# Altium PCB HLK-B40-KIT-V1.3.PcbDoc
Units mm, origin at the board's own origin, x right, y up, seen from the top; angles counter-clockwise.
Board outline 52 x 33 mm, 2 copper layers (Top Layer, Bottom Layer); 41 components, 44 nets, 164 pads, 113 vias.
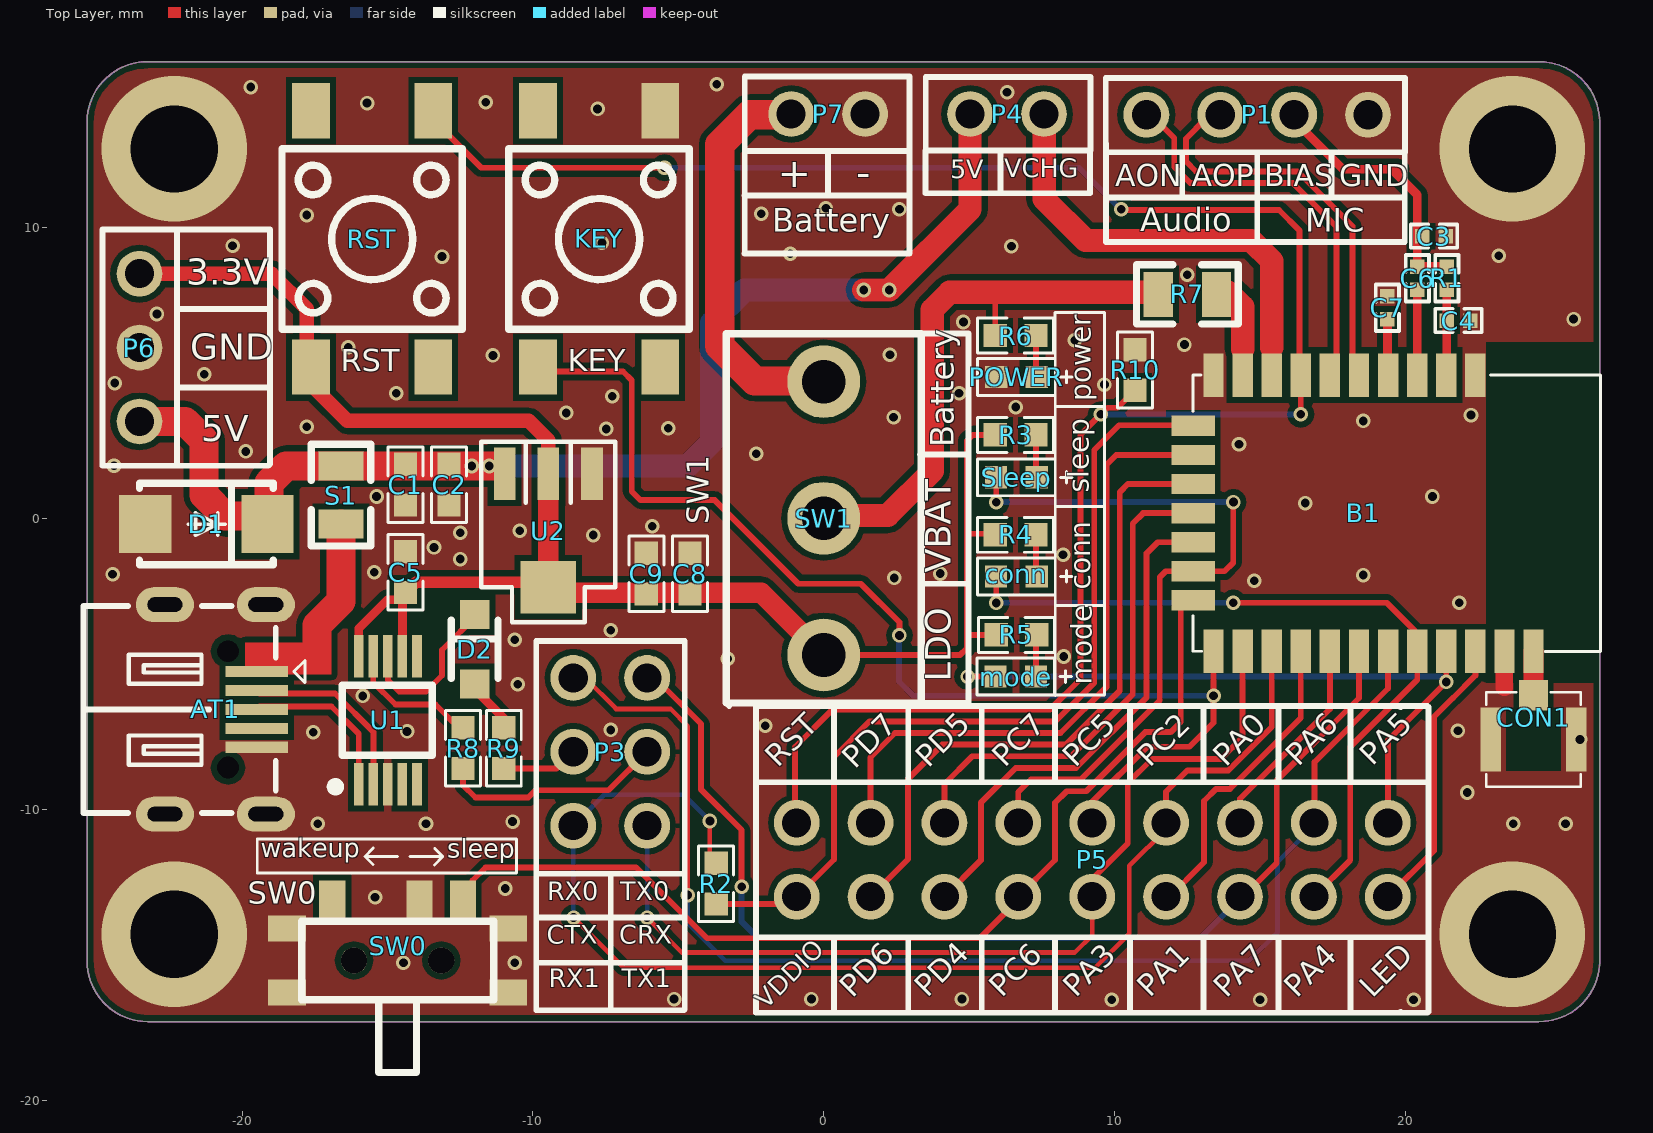
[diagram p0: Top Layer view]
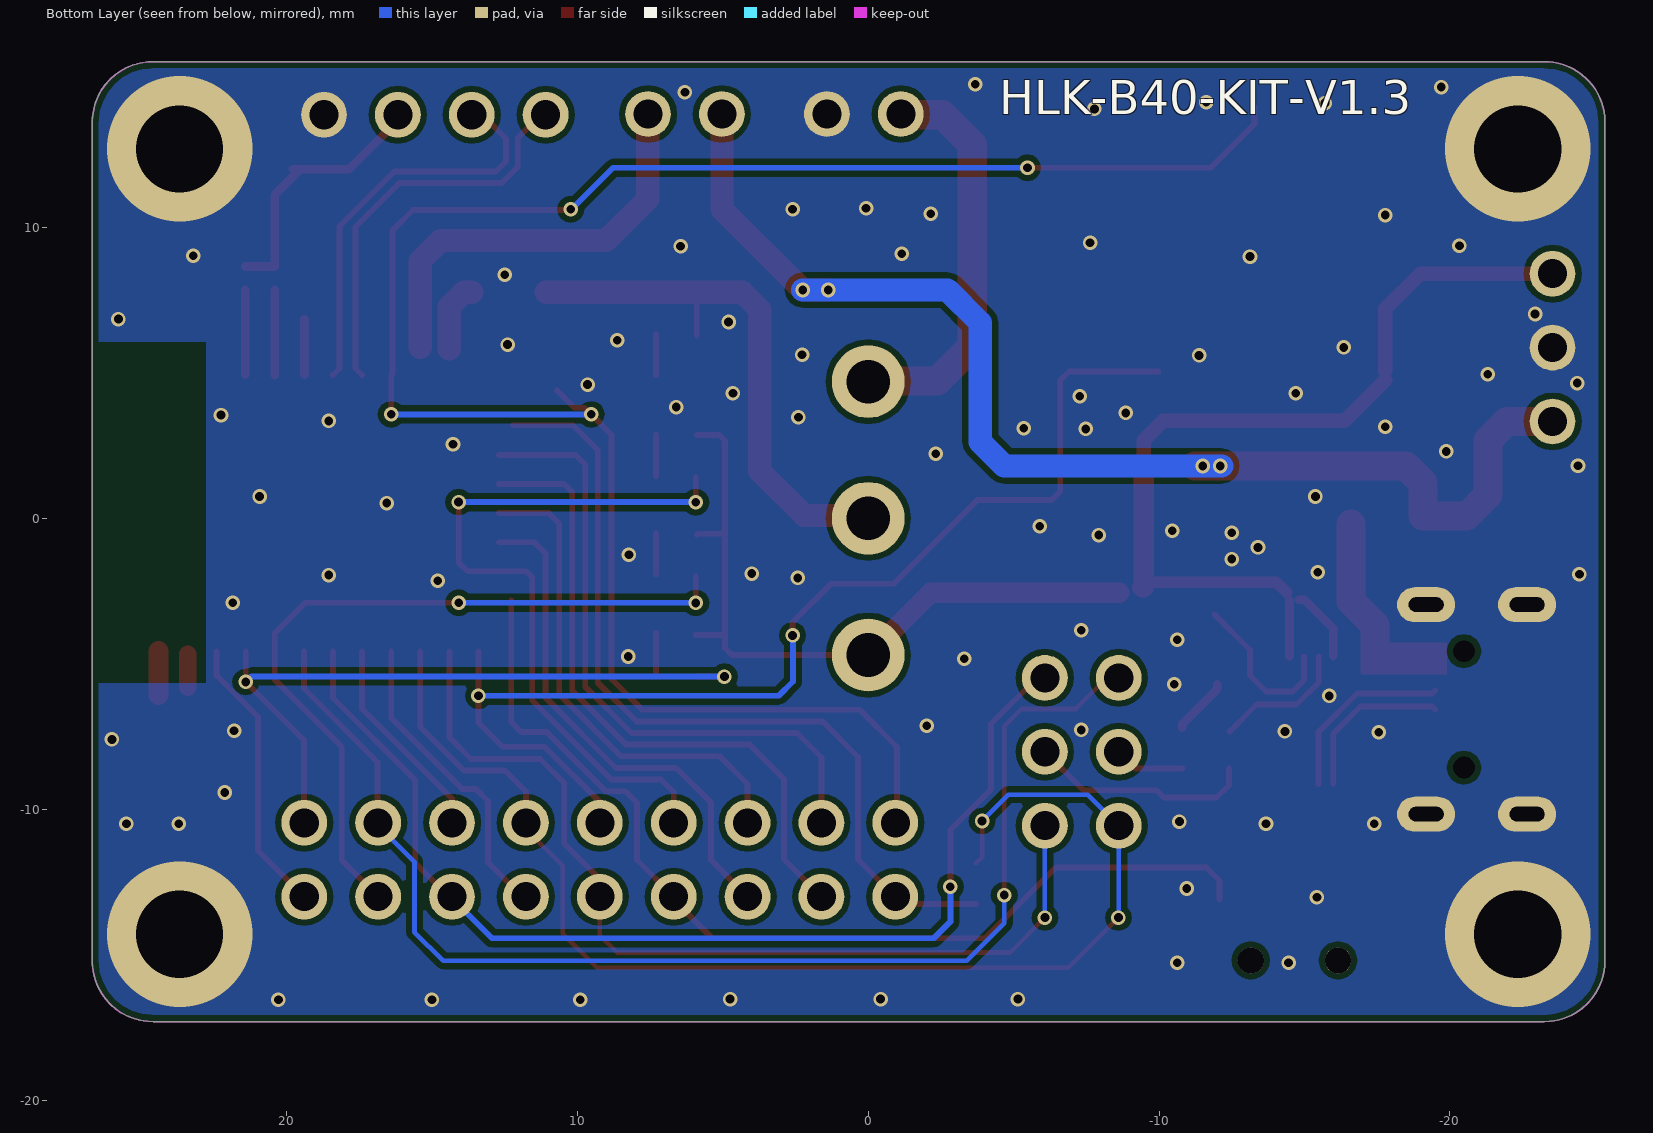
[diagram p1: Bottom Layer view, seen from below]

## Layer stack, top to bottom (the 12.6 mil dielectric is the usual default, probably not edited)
Top Solder: solder mask 0.0102, Solder Resist, Dk 3.5
Top Layer: signal copper 0.0356
Dielectric1: dielectric 0.32, FR-4, Dk 4.8
Bottom Layer: signal copper 0.0356
Bottom Solder: solder mask 0.0102, Solder Resist, Dk 3.5

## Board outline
-25.325,-15.202 -25.325,13.622 cw(c-23.248,13.623) -23.227,15.7 24.597,15.7 24.597,15.699 cw(c24.598,13.622) 26.675,13.601 26.675,-15.222 cw(c24.598,-15.223) 24.577,-17.3 -23.22,-17.3 -23.245,-17.3 cw(c-23.247,-15.223)

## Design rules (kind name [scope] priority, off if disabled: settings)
Clearance [All] p1: gap=0.2 ignorepadtopadclearanceinfootprint=FALSE except(0: Arc-Hole Track-Hole SMDPad-Hole THPad-Hole Via-Hole Fill-Hole Poly-Hole Region-Hole Text-Hole)
FabricationTestPointUsage TestPointUsage [All] p1: valid=0 allowmultiple=FALSE
FabricationTestpoint Testpoint [All] p1: side=3 testpointundercomponent=TRUE minsize=1.016 maxsize=2.54 preferedsize=1.524 minholesize=0 maxholesize=1.016 preferedholesize=0.813 testpointgrid=0.025 allowsidetop=TRUE allowsidebottom=TRUE usegrid=TRUE gridtolerance=0
PlaneConnect [All] p1: planeconnectstyle=Direct reliefexpansion=0.508 reliefentries=4 reliefconductorwidth=0.254 reliefairgap=0.254
PolygonConnect [All] p1: connectstyle=Direct reliefconductorwidth=0.254 reliefentries=4 polygonreliefangle="90 Angle" airgapwidth=0.254
RoutingVias [All] p1: holewidth=0.711 width=1.27 viastyle="Through Hole" minholewidth=0.711 minwidth=1.27 maxholewidth=0.711 maxwidth=1.27
SilkToSolderMaskClearance SilkscreenOverComponentPads [IsPad] p1: minsilkscreentomaskgap=0.254 clearancetoexposedcopper=TRUE
SolderMaskExpansion [All] p1: expansion=0 istentingtop=FALSE
Width [All] p1: maxlimit=5 minlimit=0.16 preferedwidth=0.254
26 further rules are at their usual default settings.

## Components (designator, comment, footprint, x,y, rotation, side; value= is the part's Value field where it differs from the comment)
AT1 "micro usb" USB-MICRO_D -22.65,-6.569 r270 top
B1 "B40" B40 18.55,0.175 r270 top
C1 "10UF" 0603 -14.383,1.157 r90 top
C2 "0.1UF" 0603 -12.883,1.157 r90 top
C3 "NC" 0402 20.575,9.7 r0 top
C4 "1UF" 0402 21.418,6.8 r0 top
C5 "0.1UF" 0603 -14.383,-1.851 r270 top
C6 "1UF" 0402 20.404,7.855 r90 top
C7 "1UF" 0402 19.377,6.838 r90 top
C8 "22UF" 0603 -4.6,-1.9 r270 top value=100pF
C9 "0.1UF" 0603 -6.1,-1.9 r270 top value=100pF
CON1 "1" SMA/UFLR/NI 24.4,-7.6 r180 top
conn "" 0603LED 7.324,-1.996 r180 top
D1 "1SMA4736A" SMA_L4.4-W2.8-LS5.4-RD -21.225,-0.2 r180 top
D2 "1N5819WS" SOD-323_L1.8-W1.3-LS2.5-RD -12,-4.5 r270 top
KEY "K2-1102SP-C4SC-04" KEY-SMD_4P-L6.0-W6.0-P4.50-LS9.5#1 -7.725,9.601 r90 top
mode "" 0603LED 7.3,-5.439 r180 top
P1 "Component_1" 2.54*4 14.9,13.875 r0 top
P3 "UART-change" 2.54*2*3 -7.343,-8.025 r0 top
P4 "跳线帽" 2.54*2 6.3,13.9 r0 top
P5 "Component_1" 2.54*18 7.45,-10.467 r0 top
P6 "Component_1" 2.54*3 -23.525,4.6 r90 top
P7 "Component_1" 2.54*2 0.15,13.9 r180 top
POWER "" 0603LED 7.324,4.86 r180 top
R1 "2.2K 5%" 0402 21.418,7.854 r90 top
R2 "10K 5%" 0603 -3.7,-12.561 r90 top
R3 "4.7K" 0603 6.592,2.869 r0 top
R4 "4.7K" 0603 6.592,-0.566 r0 top
R5 "4.7K" 0603 6.625,-4.006 r0 top
R6 "4.7K" 0603 6.592,6.285 r0 top
R7 "0R" R0805 12.5,7.7 r0 top
R8 "4.7K" 0603 -12.4,-7.9 r270 top
R9 "4.7K" 0603 -11,-7.9 r270 top
R10 "10K" 0603 10.7,5.1 r270 top
RST "K2-1102SP-C4SC-04" KEY-SMD_4P-L6.0-W6.0-P4.50-LS9.5#2 -15.525,9.601 r270 top
S1 "SMD0805B050TF" R0805 -16.6,0.8 r90 top
Sleep "" 0603LED 7.324,1.411 r180 top
SW0 "TA-3524A-A3" SW-SMD_3P-L6.6-W2.7-P1.50 -14.65,-14.699 r0 top
SW1 "SS-12D10L5" SW-TH_SS-12D10L5 0,0 r270 top
U1 "CH340E" MSOP-10 -14.986,-6.943 r0 top
U2 "AMS1117" 1117 -7.95,1.6 r180 top

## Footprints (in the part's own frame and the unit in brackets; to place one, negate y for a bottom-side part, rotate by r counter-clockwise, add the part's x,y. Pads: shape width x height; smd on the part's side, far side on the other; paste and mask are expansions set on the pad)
2.54*2 [mil]
  round 62 hole 39.37: 1(-50,0) 2(50,0)
  silkscreen extent -110,-49 113,50
2.54*2*3 [mil]
  round 62 hole 39.37: 1(50,100) 2(-50,100) 3(50,0) 4(-50,0) 5(50,-100) 6(-50,-100)
  silkscreen extent -100,-165 101,150
2.54*3 [mil]
  round 62 hole 39.37: 1(-50,0) 2(50,0) 3(150,0)
  silkscreen extent -110,-51 210,50
2.54*4 [mil]
  round 62 hole 39.37: 1(150,0) 2(50,0) 3(-50,0) 4(-150,0)
  silkscreen extent -205,-51 200,50
2.54*18 [mil]
  round 62 hole 39.37: 1(-330,0) 2(-330,-100) 3(-230,0) 4(-230,-100) 5(-130,0) 6(-130,-100) 7(-30,0) 8(-30,-100) 9(70,0) 10(70,-100) 11(170,0) 12(170,-100) 13(270,0) 14(270,-100) 15(370,0) 16(370,-100) 17(470,0) 18(470,-100)
  silkscreen extent -385,-155 525,55
0402 [mil]
  rect 19.69x19.69 smd: 1(0,0) 2(31.5,0)
  silkscreen extent -16,-16 47,16
0603 [mm]
  rect 0.8x0.8 smd: 1(-0.7,0) 2(0.7,0)
  silkscreen extent -1.3,-0.6 1.3,0.6
0603LED [mil] "0603贴片LED"
  rect 30x30 smd: 1(0,0) 2(55,0)
  silkscreen extent -48,-25 80,25
1117 [mm]
  rect 1.9x1.8 smd: 0(1.52,3.97)
  rect 0.75x1.8 smd: 1(0.02,0.07) 2(1.52,0.07) 3(3.02,0.07)
  silkscreen extent -0.78,-1.03 3.82,5.17, body extent -0.73,0.14 3.77,4.14, height 1.5
B40 [mm]
  rect 1.5x0.7 smd mask+0: 1(-4.75,3.85) 2(-4.75,2.85) 3(-4.75,1.85) 4(-4.75,0.85) 5(-4.75,-0.15) 6(-4.75,-1.15) 7(-4.75,-2.15) 8(-4.75,-3.15) 9(-4.75,-4.15) 10(-4.75,-5.15) 18(4.75,-5.15) 19(4.75,-4.15) 20(4.75,-3.15) 21(4.75,-2.15) 22(4.75,-1.15) 23(4.75,-0.15) 24(4.75,0.85) 25(4.75,1.85) 26(4.75,2.85) 27(4.75,3.85) 28(4.75,4.85) 29(4.75,5.85)
  rect 0.7x1.5 smd mask+0: 11(-3.004,-5.85) 12(-2.004,-5.85) 13(-1.004,-5.85) 14(-0.004,-5.85) 15(0.996,-5.85) 16(1.996,-5.85) 17(2.996,-5.85)
  silkscreen extent -4.75,-5.85 4.75,8.15
KEY-SMD_4P-L6.0-W6.0-P4.50-LS9.5#1 [mm]
  rect 1.9x1.3 smd: 1(-4.401,2.1) 2(4.407,2.1) 3(-4.401,-2.1) 4(4.407,-2.1)
  silkscreen extent -3.1,-3.1 3.1,3.1
KEY-SMD_4P-L6.0-W6.0-P4.50-LS9.5#2 [mm]
  rect 1.9x1.3 smd: 1(-4.407,2.1) 2(4.401,2.1) 3(-4.407,-2.1) 4(4.401,-2.1)
  silkscreen extent -3.1,-3.1 3.1,3.1
MSOP-10 [mm]
  rect 0.33x1.45 smd: 1(-1,-2.2) 2(-0.5,-2.2) 3(0,-2.2) 4(0.5,-2.2) 5(1,-2.2) 6(1,2.2) 7(0.5,2.2) 8(0,2.2) 9(-0.5,2.2) 10(-1,2.2)
  silkscreen extent -1.95,-2.44 1.53,1.2
R0805 [mm]
  rect 1x1.55 smd: 1(-1,0) 2(1,0)
  silkscreen extent -1.75,-1.02 1.75,1.02
SMA/UFLR/NI [mm]
  rect 1x1.05 smd: 1(0,-1.525)
  rect 0.7x2.2 smd: 2(-1.472,0.006) 3(1.475,0)
  Top Layer pour cut-out: -0.95,1.1 0.95,1.1 0.95,-1.1 0.5,-1.1 0.5,-1 -0.5,-1 -0.5,-1.1 -0.95,-1.1 -0.95,1.1
  silkscreen extent -1.63,-1.63 1.63,1.63
SMA_L4.4-W2.8-LS5.4-RD [mm]
  rect 1.8x2 smd: 1(-2.1,0) 2(2.1,0)
  silkscreen extent -2.3,-1.4 2.3,1.4
SOD-323_L1.8-W1.3-LS2.5-RD [mm]
  rect 1x1 smd: 1(-1.2,0) 2(1.2,0)
  silkscreen extent -1,-0.8 1,0.8
SW-SMD_3P-L6.6-W2.7-P1.50 [mm]
  rect 1.3x0.9 smd: 0(-3.8,-1.6) 0(-3.8,0.6) 0(3.8,-1.6) 0(3.8,0.6)
  rect 0.9x1.3 smd: 1(-2.25,1.6) 2(0.75,1.6) 3(2.25,1.6)
  round 0.9 hole 0.9 unplated: ""(-1.5,-0.5) ""(1.5,-0.5)
  silkscreen extent -3.3,-4.35 3.3,0.85
SW-TH_SS-12D10L5 [mm]
  round 2.5 hole 1.5: 1(-4.7,0) 2(0,0) 3(4.7,0)
  silkscreen extent -6.35,-3.35 6.35,3.35
USB-MICRO_D [mm] "micro型USB ，6.7*7.5*2.5mm"
  round 0 hole 0.75 unplated: 0(-2,2.17) 0(2,2.17)
  rect 0.381x2.15 smd: 1(-1.3,3.16) 2(-0.65,3.16) 3(0,3.16) 4(0.65,3.16) 5(1.3,3.16)
  oval 1.2x2 hole 0.5 slot 1.2 at 90 deg: 6(3.6,3.47) 7(3.6,0) 8(-3.6,0) 9(-3.6,3.47)
  silkscreen extent -3.56,-2.79 3.56,4.81

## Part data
AT1: library part USB-D
C1 C2 C3 C4 C5 C6 C7: library part CAP, "Capacitor"
C8 C9: library part Cap, "Capacitor"
CON1: library part KH-IPEX-K501-29, BOM_Manufacturer="Shenzhen Kinghelm Elec"
conn mode POWER Sleep: library part LED
D1: BOM_Manufacturer=LGE
D2: BOM_LCSC Assembly=Yes, BOM_Manufacturer="Guangdong Hottech"
KEY RST: BOM_Manufacturer=HRO
P1 P7: library part Component_1_1
P3 P4 U2: library part Component_1
R1 R2 R3 R4 R5 R6 R7 R8 R9 R10: library part Res1, "Resistor"
S1: BOM_Manufacturer="Brightking Elec (TAIWAN)"
SW0: BOM_Manufacturer=Yuandi
SW1: BOM_Manufacturer="XKB Enterprise"

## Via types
v1: diameter 0.5, hole 0.3, Top Layer to Bottom Layer, tented both sides, 109 vias
v2: diameter 5, hole 3, Top Layer to Bottom Layer, 4 vias

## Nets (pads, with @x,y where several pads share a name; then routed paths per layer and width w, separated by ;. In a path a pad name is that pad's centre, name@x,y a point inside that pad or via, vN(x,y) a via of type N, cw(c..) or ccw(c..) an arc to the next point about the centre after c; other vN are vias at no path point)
1.8-4.3V: R6.1 R7.1 SW1.2 | length 19
  Top Layer w0.2: 5.042,7.742 5.075,7.775 ; R6.1 5.892,7.743
  Top Layer w0.8: SW1.2@0,0.1 2.2,0.1 3.725,1.625 3.725,7.175 4.325,7.775 R7.1@11.08,7.775
5V: C1.2 C2.2 D1.1 P4.1 P6.1 S1.2 U2.3 | length 43.5
  Top Layer w0.8: v1(1.375,7.85) v1(2.25,7.85) 5.03,10.63 P4.1
  Top Layer w1: P6.1 -21.955,3.33 -21.3,2.675 -21.3,0.8 -20.575,0.075 -19.075,0.075 -19.075,1.216 -18.491,1.8 S1.2 -12.883,1.8 v1(-12.1,1.8) v1(-11.5,1.8) U2.3@-11.24,1.8
  Bottom Layer w0.8: v1@-12.15,1.8 -4.675,1.8 -3.85,2.625 -3.85,6.725 -2.725,7.85 v1(2.25,7.85)
AOUT_N: B1.6 P1.4 | length 14.6
  Top Layer w0.2: P1.4@11.055,13.7 11.425,13.7 12.05,13.075 12.05,12.075 12.6,11.525 16.125,11.525 17.625,10.025 17.625,9.075 ; B1.6 17.625,5.15 17.625,9.775
AOUT_P: B1.5 P1.3 | length 14
  Top Layer w0.2: P1.3@13.595,13.7 13.1,13.7 12.45,13.05 12.45,12.275 12.8,11.925 16.291,11.925 18.175,10.041 18.175,9.791 18.175,5.15 B1.5
BATTERY: P7.2 SW1.1 | length 14
  Top Layer w1: P7.2@-1.12,13.7 -1.295,13.875 -2.55,13.875 -3.575,12.85 -3.575,5.925 -2.375,4.725 -0.55,4.725 SW1.1@-0.1,4.275
CH340E_RXD: R8.1 U1.9 | length 4.7
  Top Layer w0.2: U1.9 -15.486,-5.64 -14.725,-6.4 -13.35,-6.4 R8.1@-12.425,-7.325
CH340E_RXD_1: P3.3 R8.2 | length 7.7
  Top Layer w0.2: R8.2 -12.4,-9.175 -11.975,-9.6 -10.158,-9.6 -9.908,-9.35 -7.397,-9.35 P3.3
CH340E_TXD: D2.2 R9.1 | length 2
  Top Layer w0.3: D2.2 -12,-5.875 -10.8,-7.075 R9.1@-10.8,-7.2
CH340E_TXD_1: P3.4 R9.2 | length 2.4
  Top Layer w0.2: R9.2@-10.8,-8.6 -9.187,-8.6 P3.4
DM1: AT1.2 U1.2 | length 6.4
  Top Layer w0.2: AT1.2 -19.39,-6.019 -16.806,-6.019 -15.475,-7.35 -15.475,-9.132 U1.2
DP1: AT1.3 U1.1 | length 5.7
  Top Layer w0.2: AT1.3 -19.39,-6.469 -16.922,-6.469 -15.986,-7.405 U1.1
GND: AT1.5 AT1.6 AT1.7 AT1.8 AT1.9 B1.1 B1.10 B1.28 C1.1 C2.1 C3.2 C4.2 C5.1 C7.2 C8.1 C9.1 CON1.2 CON1.3 D1.2 KEY.4 P1.1 P6.2 P7.1 POWER.2 R10.1 SW0.0 SW0.2 U1.3 U2.1 | length 1.3
  Top Layer w0.4: B1.28@23.3,-4.675 B1.28
  Top Layer w0.6: 23.4,-5.8 B1.28@23.4,-4.675
  other v1: 9.9,-16.55 15,-16.55 20.275,-16.55 -5.146,-16.527 -0.425,-16.525 4.75,-16.525 -14.45,-15.275 -10.625,-15.275 -15.425,-13.025 -10.95,-12.725 -17.4,-10.5 -13.675,-10.5 23.7,-10.5 25.5,-10.5 -10.7,-10.425 22.125,-9.425 26,-7.6 -17.55,-7.35 -14.325,-7.325 21.8,-7.3 -7.325,-7.275 -2.013,-7.134 -15.852,-6.106 -10.525,-5.7 -3.3,-4.825 8.25,-4.75 -10.625,-4.175 -7.325,-3.85 21.85,-2.9 14.8,-2.15 2.425,-2.05 18.55,-1.95 -24.45,-1.925 4,-1.9 -15.45,-1.85 -12.5,-1.4 8.225,-1.25 -13.4,-1 -7.925,-0.575 -12.5,-0.5 -10.45,-0.425 -5.9,-0.275 16.55,0.525 -15.375,0.75 20.925,0.75 -24.4,1.806 -2.325,2.225 -19.875,2.3 14.275,2.55 -7.475,3.075 -5.35,3.1 -17.775,3.15 18.55,3.35 2.4,3.475 22.25,3.55 -8.85,3.625 6.6,3.825 -7.275,4.2 -14.7,4.3 4.65,4.3 9.65,4.6 -24.375,4.65 -21.3,4.95 -11.375,5.6 2.275,5.625 -16.35,5.875 12.4,5.975 8.625,6.125 4.8,6.75 25.775,6.85 -22.925,7.025 12.5,8.375 -13.125,9 23.2,9.025 -1.15,9.1 6.45,9.35 -20.325,9.375 -7.625,9.475 -17.775,10.425 -2.15,10.475 2.6,10.625 0.075,10.658 -7.775,14.075 -15.7,14.275 -11.625,14.3 6.3,14.65 -19.7,14.825 -3.675,14.925
  other v2: -22.325,-14.3 23.675,-14.3 -22.325,12.7 23.675,12.7
LDO: C5.2 C8.2 C9.2 P6.3 R3.1 R4.1 R5.1 RST.4 SW1.3 U1.7 U1.10 U2.0 U2.2 | length 57.5
  Top Layer w0.2: RST.4@-17.775,4.75 RST.4@-17.775,5.051 ; SW1.3@0.125,-4.825 SW1.3 4.675,-4.7 ; 4.675,-4.706 4.925,-4.456 4.925,-0.531 ; 4.925,-4.006 R5.1 ; R4.1 5.858,-0.531 4.925,-0.531 ; R3.1 5.125,2.869 4.925,2.669 4.925,-0.531
  Top Layer w0.3: U1.10 -15.986,-3.786 -15,-2.8 -14.8,-2.8 ; U1.7 C5.2@-14.486,-2.814
  Top Layer w0.4: C5.2 -14.031,-2.2 -9.64,-2.2 U2.0
  Top Layer w0.5: P6.3 -18.985,8.41 -17.775,7.2 RST.4@-17.775,5.051 ; RST.4@-17.775,4.75 -16.375,3.35 -10.136,3.35 -9.47,2.684 U2.2
  Top Layer w0.7: U2.2 U2.0 U2.0@-9.42,-2.37 ; U2.0@-8.637,-2.553 -2.147,-2.553 SW1.3
LED: B1.27 P5.18 | length 9.7
  Top Layer w0.2: P5.18@19.39,-13.01 20.975,-11.425 20.975,-6.825 21.625,-6.175 21.628,-6.175 22.4,-5.403 B1.27
NetAT1_1: AT1.1 S1.1 | length 4.8
  Top Layer w1: -17.425,-4.7 -17.425,-3.675 -16.6,-2.85 S1.1
NetB1_2: B1.2 C4.1 R1.1 | length 2.9
  Top Layer w0.3: B1.2@21.418,4.943 R1.1
NetB1_3: B1.3 C6.1 | length 2.9
  Top Layer w0.3: B1.3@20.404,4.929 C6.1
NetB1_4: B1.4 C7.1 | length 1.9
  Top Layer w0.3: B1.4@19.377,4.948 C7.1
NetB1_9: B1.9 R7.2 | length 2.4
  Top Layer w0.8: R7.2@13.62,7.775 13.9,7.775 14.4,7.275 14.4,5.825
NetB1_29: B1.29 CON1.1 | length 1.5
  Top Layer w0.7: CON1.1 B1.29
NetC3_1: C3.1 C6.2 P1.2 R1.2 | length 9.1
  Top Layer w0.3: P1.2@16.135,13.7 16.15,13.7 17.85,12 19.775,12 ; 19.525,12 20.404,11.121 C6.2 21.416,8.655 R1.2
Netconn_1: conn.1 R4.2 | length 1.4
  Top Layer w0.2: conn.1@7.3,-1.924 R4.2@7.3,-0.526
NetD2_1: D2.1 U1.8 | length 5.7
  Top Layer w0.2: U1.8 -14.986,-5.557 -14.592,-5.95 -13.675,-5.95 -13.125,-5.4 -13.125,-4.525 D2.1@-11.9,-3.3
Netmode_1: mode.1 R5.2 | length 1.4
  Top Layer w0.2: mode.1@7.3,-5.339 R5.2@7.3,-3.934
NetPOWER_1: POWER.1 R6.2 | length 1.4
  Top Layer w0.2: POWER.1@7.3,4.931 R6.2@7.3,6.324
NetR3_2: R3.2 Sleep.1 | length 1.4
  Top Layer w0.2: Sleep.1@7.3,1.45 R3.2@7.3,2.878
PA0: B1.22 P5.13 | length 7.2
  Top Layer w0.2: P5.13 14.308,-9.642 17.4,-6.55 B1.22
PA1: B1.21 P5.12 | length 10.7
  Top Layer w0.2: P5.12@11.831,-13.069 13.075,-11.825 13.075,-9.72 13.495,-9.3 13.966,-9.3 16.4,-6.866 B1.21
PA2: B1.20 P3.6 P5.11 R2.2 | length 43
  Top Layer w0.16: v1(-8.6,-13.725) -6.875,-15.45 9.325,-15.45 10.5,-14.275 10.5,-11.951 11.768,-10.683 P5.11 ; v1(-3.915,-10.405) -3.915,-11.646 R2.2
  Top Layer w0.2: P5.11 11.768,-9.402 12.5,-8.67 13.905,-8.67 15.4,-7.175 B1.20
  Bottom Layer w0.16: v1@-8.613,-13.663 P3.6 -7.545,-9.498 -4.81,-9.498 -3.915,-10.393 v1(-3.915,-10.405)
PA3: B1.19 P3.5 P5.10 | length 31.8
  Top Layer w0.16: v1(-6.075,-13.725) -4.875,-14.925 8.629,-14.925 9.228,-14.326 P5.10
  Top Layer w0.2: P5.10@9.228,-12.397 10.45,-11.175 10.45,-9.1 11.28,-8.27 13.655,-8.27 14.4,-7.525 B1.19
  Bottom Layer w0.16: v1@-6.073,-13.677 P3.5
PA4: B1.25 conn.2 P5.16 | length 26.3
  Top Layer w0.2: v1(5.927,-2.907) conn.2 ; v1(14.075,-2.902) 19.352,-2.902 20.4,-3.95 B1.25 20.4,-5.55 18.1,-7.85 18.1,-11.75 P5.16@16.845,-13.005
  Bottom Layer w0.2: v1@5.927,-2.902 v1(14.075,-2.902)
PA5: B1.26 mode.2 P5.17 | length 24.3
  Top Layer w0.2: v1(4.942,-5.439) mode.2 ; P5.17@19.4,-10.5 19.4,-7.625 v1(21.4,-5.625) B1.26
  Bottom Layer w0.2: v1@4.942,-5.433 21.207,-5.433 v1(21.4,-5.625)
PA6: B1.24 P3.2 P5.15 | length 43.8
  Top Layer w0.16: P3.2 -8.208,-5.485 -7.14,-6.553 -5.269,-6.553 -4.675,-7.146 v1(-4.675,-12.95)
  Top Layer w0.2: P5.15@16.875,-10.5 16.875,-8.375 19.4,-5.85 B1.24
  Bottom Layer w0.16: v1(-4.675,-12.95) -4.675,-13.6 -4.675,-13.925 -3.387,-15.213 14.612,-15.213 15.6,-14.225 15.6,-11.8 P5.15@16.89,-10.51
PA7: B1.23 P3.1 P5.14 | length 38
  Top Layer w0.2: P3.1 -5.799,-5.485 -4.216,-7.068 -4.216,-9.326 -2.824,-10.718 v1(-2.824,-12.669) ; P5.14@14.363,-13.062 15.575,-11.85 15.575,-9 18.4,-6.175 B1.23
  Bottom Layer w0.2: v1(-2.824,-12.669) -2.824,-13.87 -2.257,-14.437 12.938,-14.437 P5.14@14.338,-13.037
PC5: B1.18 KEY.1 P5.9 | length 39.9
  Top Layer w0.2: KEY.1@-9.975,5.051 -6.901,5.051 -6.6,4.75 -6.6,0.925 -6.3,0.625 -3.75,0.625 -0.875,-2.25 1.275,-2.25 2.6,-3.575 v1(2.6,-4.025) ; P5.9 9.228,-9.747 11.125,-7.85 12.575,-7.85 13.4,-7.025 B1.18
  Bottom Layer w0.2: v1@2.588,-4.038 2.588,-5.613 3.075,-6.1 v1(13.4,-6.1)
PC6: B1.17 P5.8 SW0.3 | length 34.7
  Top Layer w0.2: SW0.3@-12.075,-13.099 -12.075,-12.45 -11.625,-12 -6.45,-12 -4.013,-14.437 5.363,-14.437 6.688,-13.112 P5.8 7.95,-11.745 7.95,-9.78 8.35,-9.38 9.02,-9.38 11.05,-7.35 11.925,-7.35 12.275,-7 B1.17@12.275,-2.825
PC7: B1.16 P5.7 Sleep.2 | length 25.3
  Top Layer w0.2: v1(5.927,0.552) Sleep.2 ; P5.7 6.688,-9.412 7.12,-8.98 8.836,-8.98 11.55,-6.266 11.55,-2.025 11.754,-1.821 B1.16 13.779,-1.821 14.075,-1.525 14.075,0.55 v1(14.083,0.558)
  Bottom Layer w0.2: v1@5.927,0.558 v1(14.083,0.558)
PD4: B1.15 P5.6 | length 17.7
  Top Layer w0.2: P5.6 5.4,-11.755 5.4,-9.78 6.6,-8.58 8.67,-8.58 11.1,-6.15 11.1,-1.2 11.479,-0.821 B1.15
PD5: B1.14 P5.5 | length 17.2
  Top Layer w0.2: P5.5 4.148,-9.132 5.1,-8.18 8.495,-8.18 10.625,-6.05 10.625,-0.175 10.979,0.179 B1.14
PD6: B1.13 P5.4 | length 22.6
  Top Layer w0.2: P5.4 2.9,-11.715 2.9,-8.955 4.075,-7.78 8.32,-7.78 10.175,-5.925 10.175,0.9 10.454,1.179 B1.13
PD7: B1.12 P5.3 | length 22.1
  Top Layer w0.2: P5.3 1.608,-8.222 2.45,-7.38 8.136,-7.38 9.725,-5.791 9.725,1.85 10.054,2.179 B1.12
RSTP: B1.7 P5.1 R10.2 RST.1 | length 69.2
  Top Layer w0.2: RST.1@-13.275,14.151 -13.275,13.551 -11.774,12.05 v1(-5.475,12.05) ; P5.1 -0.986,-10.413 -0.986,-7.861 0.295,-6.58 7.77,-6.58 8.825,-5.525 8.825,2.875 v1(9.525,3.575) 9.75,3.8 10.1,3.8 R10.2 ; v1@10.225,10.6 15.65,10.6 16.35,9.9 B1.7@16.35,4.975 ; v1(16.4,3.575) B1.7
  Bottom Layer w0.2: v1(-5.475,12.05) 8.775,12.05 v1@10.225,10.6 ; v1(9.525,3.575) v1(16.4,3.575)
  other v1: 10.225,10.625
VCHG: B1.8 P4.2 | length 14.6
  Top Layer w0.8: P4.2@7.575,13.85 7.575,10.975 9,9.55 14.7,9.55 15.4,8.85 15.4,5.875
VDDIO: B1.11 P5.2 R2.1 | length 29.5
  Top Layer w0.2: R2.1 -1.186,-13.261 0.35,-11.725 0.35,-8.205 1.575,-6.98 7.97,-6.98 9.3,-5.65 9.3,2.35 10.15,3.2 B1.11@12.221,3.2
pads on no net: AT1.0 AT1.4 KEY.2 KEY.3 RST.2 RST.3 SW0. SW0.1 U1.4 U1.5 U1.6

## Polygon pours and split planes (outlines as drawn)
GND on Top Layer "Top-No Net" (solid, remove dead copper, pour order 1000): -26.269,16.692 -26.269,-18.683 -26.194,-18.758 28.406,-18.758 28.406,16.467
GND on Bottom Layer "Top-No Net" (solid, remove dead copper, pour order 1001): -25.625,17.8 -25.625,-18.7 -25.975,-19.05 29.575,-19.05 29.8,-19.275 29.8,17.35 28.325,18.825 27.75,18.25 -25.3,18.25

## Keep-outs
Keep-Out Layer:
  lines w0.05: -25.325,-15.202 -25.325,13.622 cw(c-23.248,13.623) -23.227,15.7 24.597,15.7 ; -25.324,-15.202 ccw(c-23.247,-15.223) -23.245,-17.3 24.578,-17.3 ; 24.577,-17.3 ccw(c24.598,-15.223) 26.675,-15.222 26.675,13.601 ccw(c24.598,13.622) 24.597,15.699

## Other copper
Top Layer:
  rectangle net NetAT1_1: -19.89,-5.369 -16.925,-4.269
  pour cut-out: 26.675,-5.65 26.65,-5.675 22.75,-5.675 22.75,6.05 22.775,6.075 26.65,6.075 26.675,6.05
Bottom Layer:
  pour cut-out: 26.675,-5.65 26.65,-5.675 22.75,-5.675 22.75,6.05 22.775,6.075 26.65,6.075 26.675,6.05

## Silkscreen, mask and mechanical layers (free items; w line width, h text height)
Top Overlay:
  lines w0.1: -15.5,-11.9 -15.775,-11.625 ; -15.488,-11.337 -15.775,-11.625 ; -14.65,-11.625 -15.775,-11.625 ; -14.225,-11.625 -13.1,-11.625 ; -13.387,-11.913 -13.1,-11.625 ; -13.375,-11.35 -13.1,-11.625 ; 7.935,-6.074 9.65,-6.074 9.65,7.075 7.956,7.075 7.956,6.859 7.959,6.857 7.959,-6.1 ; 7.959,-3 9.65,-3 ; 7.959,0.4 9.65,0.4 ; 7.959,3.85 9.625,3.85 ; -19.477,-12.198 -19.477,-11.025 -10.562,-11.025 -10.562,-12.198 -19.477,-12.198
  lines w0.2: -22.234,1.806 -19.094,1.806 -19.034,1.866 -19.034,9.934 -22.234,9.934 ; -22.234,4.5 -19.034,4.5 ; -22.234,7.2 -19.034,7.2 ; -9.883,-15.275 -4.857,-15.275 ; -9.883,-13.725 -4.807,-13.725 ; -9.883,-12.216 -9.883,-16.908 -4.806,-16.908 -4.782,-16.884 -4.782,-12.216 ; -7.325,-16.908 -7.325,-12.216 ; -3.279,-6.421 -3.25,-6.45 ; -2.725,9.1 2.95,9.1 2.95,11.1 ; -2.725,11.1 2.95,11.1 ; -2.714,9.1 -2.714,11.1 -2.714,12.632 ; -2.329,-14.404 -2.329,-16.996 20.754,-16.996 ; -2.329,-9.07 -2.329,-6.421 ; -2.3,-6.45 20.745,-6.45 ; 0.149,11.1 0.149,12.632 ; 0.35,-16.996 0.35,-14.404 ; 0.35,-9.07 0.35,-6.478 ; 2.11,11.1 2.95,11.1 ; 2.904,-16.996 2.904,-14.404 ; 2.904,-9.07 2.904,-6.478 ; 2.944,11.098 2.944,12.63 ; 3.025,-6.35 4.975,-6.35 4.975,6.35 3.35,6.35 ; 3.3,2.2 4.875,2.2 ; 3.35,-2.25 4.975,-2.25 ; 3.5,12.65 3.5,11.175 9.15,11.175 9.15,12.559 ; 5.429,-16.971 5.429,-14.404 ; 5.429,-9.045 5.429,-6.478 ; 6.074,11.175 6.074,12.559 ; 7.954,-16.971 7.954,-14.404 ; 7.954,-9.045 7.954,-6.478 ; 9.7,12.875 9.7,9.5 14.9,9.5 ; 9.8,11.025 14.9,11.025 19.875,11.025 ; 10.529,-16.946 10.529,-14.404 ; 10.529,-9.02 10.529,-6.478 ; 12.325,11.075 12.325,12.584 ; 13.054,-16.946 13.054,-14.404 ; 13.054,-9.02 13.054,-6.478 ; 14.9,12.509 14.9,9.5 ; 15.629,-16.946 15.629,-14.404 ; 15.629,-9.02 15.629,-6.478 ; 17.45,11.025 17.45,12.509 ; 18.104,-16.996 18.104,-14.404 ; 18.104,-9.07 18.104,-6.478 ; 19.795,-6.45 19.835,-6.49 ; 19.804,-16.996 19.835,-16.965 ; 19.975,12.825 19.975,9.5 14.9,9.5 ; 20.785,-16.965 20.785,-13.85 ; 20.785,-9.07 20.785,-6.49
  text "VCHG" at 6.199,11.5 h1.1
  text "5V" at 4.35,11.475 h1.1
  text "AON" at 10.025,11.425 h0.75
  text "AOP" at 12.65,11.425 h0.75
  text "BIAS" at 15.15,11.425 h0.75
  text "GND" at 17.725,11.425 h0.75
  text "-" at 1.125,11.4 h1
  text "+" at -1.575,11.375 h1
  text "Audio" at 10.875,9.875 h0.8
  text "Battery" at -1.775,9.85 h0.8
  text "MIC" at 16.55,9.85 h0.8
  text "3.3V" at -21.925,8.025 h0.9
  text "GND" at -21.775,5.45 h0.9
  text "RST" at -16.6,4.8 h1.3
  text "KEY" at -8.8,4.8 h1.3
  text "power" at 9.425,4.025 h1.2 r90
  text "5V" at -21.4,2.65 h0.9
  text "Battery" at 4.475,2.45 h0.8 r90
  text "sleep" at 9.35,0.875 h1.2 r90
  text "SW1" at -3.7,-0.2 h1.3 r90
  text "VBAT" at 4.65,-1.875 h1.5 r90
  text "conn" at 9.4,-2.45 h1.2 r90
  text "LDO" at 4.65,-5.625 h1.5 r90
  text "mode" at 9.45,-5.724 h1.2 r90
  text "PA5" at 19.038,-8.737 h1.3 r45
  text "PA6" at 16.5,-8.745 h1.3 r45
  text "RST" at -1.4,-8.775 h1.3 r45
  text "PC7" at 6.412,-8.788 h1.3 r45
  text "PC5" at 8.837,-8.788 h1.3 r45
  text "PC2" at 11.399,-8.776 h1.3 r45
  text "PA0" at 14,-8.77 h1.3 r45
  text "PD5" at 3.775,-8.8 h1.3 r45
  text "PD7" at 1.258,-8.825 h1.3 r45
  text "wakeup" at -19.35,-11.875 h1.1
  text "sleep" at -12.95,-11.9 h1.1
  text "RX0" at -9.503,-13.35 h1.1
  text "TX0" at -7,-13.35 h1.1
  text "SW0" at -19.8,-13.5 h1.3
  text "CTX" at -9.525,-14.85 h1.1
  text "CRX" at -7.025,-14.85 h1.1
  text "RX1" at -9.45,-16.35 h1.1
  text "TX1" at -6.95,-16.35 h1.1
  text "PD6" at 1.175,-16.7 h1.3 r45
  text "PD4" at 3.75,-16.691 h1.3 r45
  text "PC6" at 6.3,-16.691 h1.3 r45
  text "PA3" at 8.85,-16.691 h1.3 r45
  text "PA1" at 11.4,-16.691 h1.3 r45
  text "PA7" at 14.025,-16.7 h1.3 r45
  text "PA4" at 16.45,-16.7 h1.3 r45
  text "LED" at 19.05,-16.7 h1.3 r45
  text "VDDIO" at -1.825,-17.067 h1.1 r45
Bottom Overlay:
  text "HLK-B40-KIT-V1.3" at -4.5,13.5 h2
Top Solder:
  rectangle: -16.251,-5.5 -13.7,-3.967
  rectangle: -14.7,-9.967 -13.721,-8.3
  rectangle: -16.291,-10 -15.2,-8.318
